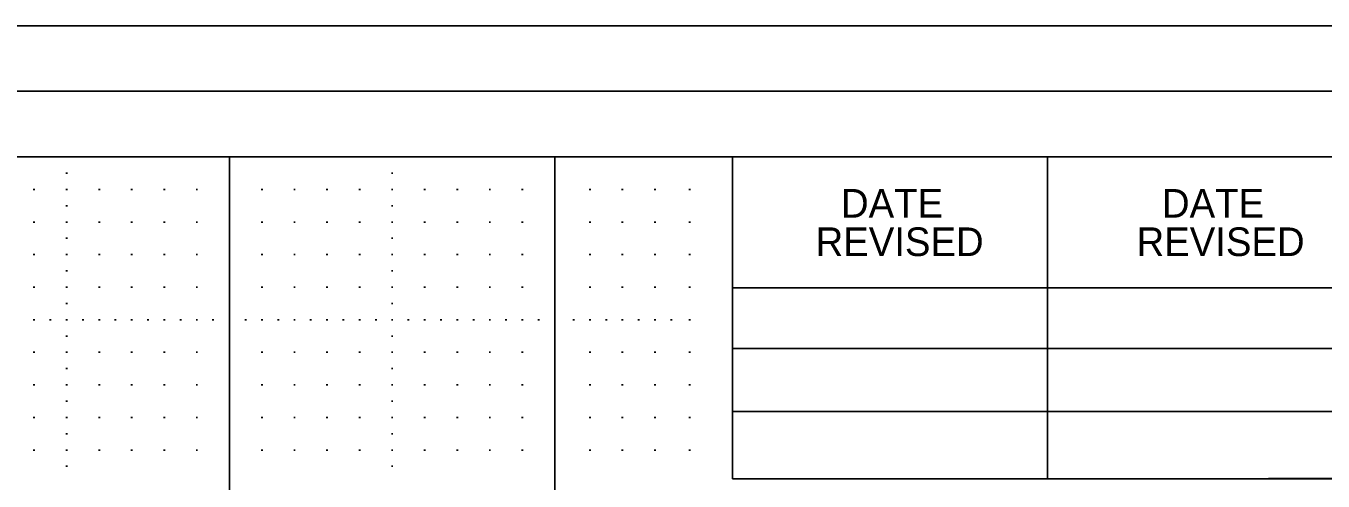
# Model space of a CAD drawing. Extents: x -3.6 to 32.1, y -0.4 to 25.6.
# Drawn here: x 23.183 to 27.168, y 19.55 to 20.947 of the extents above; entities that cross this region are included whole.
import ezdxf

# ---------------------------------------------------------------- set-up
doc = ezdxf.new("R2010")
doc.units = 0
for name, color, linetype in [('Level 1', 7, 'Continuous'), ('Level 4', 7, 'Continuous'), ('Level 5', 7, 'Continuous'), ('Level 62', 7, 'Continuous'), ('Level 63', 7, 'Continuous'), ('Level 63 Full', 7, 'Continuous'), ('R_Border Prem', 7, 'Continuous')]:
    doc.layers.add(name, color=color, linetype=linetype)

msp = doc.modelspace()

# ---------------------------------------------------------------- linework, layer by layer
at = {"layer": 'Level 1'}
for p, q in [((25.353, 19.5569), (25.353, 20.5449)), ((26.321, 19.5569), (26.321, 20.545)), ((25.353, 20.1429), (27.307, 20.1429)), ((25.353, 19.9569), (27.307, 19.9569)), ((25.353, 19.7629), (27.307, 19.7629)), ((31.617, 19.5569), (25.353, 19.5569))]:
    msp.add_line(p, q, dxfattribs=at)
at = {"layer": 'Level 4'}
for p, q in [((23.808, 0.545), (23.808, 20.545)), ((24.808, 0.545), (24.808, 20.5449))]:
    msp.add_line(p, q, dxfattribs=at)
at = {"layer": 'Level 5'}
for p, q in [((23.3055, 20.495), (23.3105, 20.495)), ((24.3055, 20.495), (24.3105, 20.495)), ((23.2055, 20.445), (23.2105, 20.445)), ((23.3055, 20.445), (23.3105, 20.445)), ((23.4055, 20.445), (23.4105, 20.445)), ((23.5055, 20.445), (23.5105, 20.445)), ((23.6055, 20.445), (23.6105, 20.445)), ((23.7055, 20.445), (23.7105, 20.445)), ((23.9055, 20.445), (23.9105, 20.445)), ((24.0055, 20.445), (24.0105, 20.445)), ((24.1055, 20.445), (24.1105, 20.445)), ((24.2055, 20.445), (24.2105, 20.445)), ((24.3055, 20.445), (24.3105, 20.445)), ((24.4055, 20.445), (24.4105, 20.445)), ((24.5055, 20.445), (24.5105, 20.445)), ((24.6055, 20.445), (24.6105, 20.445)), ((24.7055, 20.445), (24.7105, 20.445)), ((24.913, 20.445), (24.918, 20.445)), ((25.013, 20.445), (25.018, 20.445)), ((25.113, 20.445), (25.118, 20.445)), ((25.219, 20.445), (25.224, 20.445)), ((23.3055, 20.395), (23.3105, 20.395)), ((24.3055, 20.395), (24.3105, 20.395)), ((23.2055, 20.345), (23.2105, 20.345)), ((23.3055, 20.345), (23.3105, 20.345)), ((23.4055, 20.345), (23.4105, 20.345)), ((23.5055, 20.345), (23.5105, 20.345)), ((23.6055, 20.345), (23.6105, 20.345)), ((23.7055, 20.345), (23.7105, 20.345)), ((23.9055, 20.345), (23.9105, 20.345)), ((24.0055, 20.345), (24.0105, 20.345)), ((24.1055, 20.345), (24.1105, 20.345)), ((24.2055, 20.345), (24.2105, 20.345)), ((24.3055, 20.345), (24.3105, 20.345)), ((24.4055, 20.345), (24.4105, 20.345)), ((24.5055, 20.345), (24.5105, 20.345)), ((24.6055, 20.345), (24.6105, 20.345)), ((24.7055, 20.345), (24.7105, 20.345)), ((24.913, 20.345), (24.918, 20.345)), ((25.013, 20.345), (25.018, 20.345)), ((25.113, 20.345), (25.118, 20.345)), ((25.219, 20.345), (25.224, 20.345)), ((23.3055, 20.295), (23.3105, 20.295)), ((24.3055, 20.295), (24.3105, 20.295)), ((23.2055, 20.245), (23.2105, 20.245)), ((23.3055, 20.245), (23.3105, 20.245)), ((23.4055, 20.245), (23.4105, 20.245)), ((23.5055, 20.245), (23.5105, 20.245)), ((23.6055, 20.245), (23.6105, 20.245)), ((23.7055, 20.245), (23.7105, 20.245)), ((23.9055, 20.245), (23.9105, 20.245)), ((24.0055, 20.245), (24.0105, 20.245)), ((24.1055, 20.245), (24.1105, 20.245)), ((24.2055, 20.245), (24.2105, 20.245)), ((24.3055, 20.245), (24.3105, 20.245)), ((24.4055, 20.245), (24.4105, 20.245)), ((24.5055, 20.245), (24.5105, 20.245)), ((24.6055, 20.245), (24.6105, 20.245)), ((24.7055, 20.245), (24.7105, 20.245)), ((24.913, 20.245), (24.918, 20.245)), ((25.013, 20.245), (25.018, 20.245)), ((25.113, 20.245), (25.118, 20.245)), ((25.219, 20.245), (25.224, 20.245)), ((23.3055, 20.195), (23.3105, 20.195)), ((24.3055, 20.195), (24.3105, 20.195)), ((23.2055, 20.145), (23.2105, 20.145)), ((23.3055, 20.145), (23.3105, 20.145)), ((23.4055, 20.145), (23.4105, 20.145)), ((23.5055, 20.145), (23.5105, 20.145)), ((23.6055, 20.145), (23.6105, 20.145)), ((23.7055, 20.145), (23.7105, 20.145)), ((23.9055, 20.145), (23.9105, 20.145)), ((24.0055, 20.145), (24.0105, 20.145)), ((24.1055, 20.145), (24.1105, 20.145)), ((24.2055, 20.145), (24.2105, 20.145)), ((24.3055, 20.145), (24.3105, 20.145)), ((24.4055, 20.145), (24.4105, 20.145)), ((24.5055, 20.145), (24.5105, 20.145)), ((24.6055, 20.145), (24.6105, 20.145)), ((24.7055, 20.145), (24.7105, 20.145)), ((24.913, 20.145), (24.918, 20.145)), ((25.013, 20.145), (25.018, 20.145)), ((25.113, 20.145), (25.118, 20.145)), ((25.219, 20.145), (25.224, 20.145)), ((23.3055, 20.095), (23.3105, 20.095)), ((24.3055, 20.095), (24.3105, 20.095)), ((23.2055, 20.045), (23.2105, 20.045)), ((23.2555, 20.045), (23.2605, 20.045)), ((23.3055, 20.045), (23.3105, 20.045)), ((23.3555, 20.045), (23.3605, 20.045)), ((23.4055, 20.045), (23.4105, 20.045)), ((23.4555, 20.045), (23.4605, 20.045)), ((23.5055, 20.045), (23.5105, 20.045)), ((23.5555, 20.045), (23.5605, 20.045)), ((23.6055, 20.045), (23.6105, 20.045)), ((23.6555, 20.045), (23.6605, 20.045)), ((23.7055, 20.045), (23.7105, 20.045)), ((23.7555, 20.045), (23.7605, 20.045)), ((23.8555, 20.045), (23.8605, 20.045)), ((23.9055, 20.045), (23.9105, 20.045)), ((23.9555, 20.045), (23.9605, 20.045)), ((24.0055, 20.045), (24.0105, 20.045)), ((24.0555, 20.045), (24.0605, 20.045)), ((24.1055, 20.045), (24.1105, 20.045)), ((24.1555, 20.045), (24.1605, 20.045)), ((24.2055, 20.045), (24.2105, 20.045)), ((24.2555, 20.045), (24.2605, 20.045)), ((24.3055, 20.045), (24.3105, 20.045)), ((24.3555, 20.045), (24.3605, 20.045)), ((24.4055, 20.045), (24.4105, 20.045)), ((24.4555, 20.045), (24.4605, 20.045)), ((24.5055, 20.045), (24.5105, 20.045)), ((24.5555, 20.045), (24.5605, 20.045)), ((24.6055, 20.045), (24.6105, 20.045)), ((24.6555, 20.045), (24.6605, 20.045)), ((24.7055, 20.045), (24.7105, 20.045)), ((24.7555, 20.045), (24.7605, 20.045)), ((24.863, 20.045), (24.868, 20.045)), ((24.913, 20.045), (24.918, 20.045)), ((24.963, 20.045), (24.968, 20.045)), ((25.013, 20.045), (25.018, 20.045)), ((25.063, 20.045), (25.068, 20.045)), ((25.113, 20.045), (25.118, 20.045)), ((25.163, 20.045), (25.168, 20.045)), ((25.219, 20.045), (25.224, 20.045)), ((23.3055, 19.995), (23.3105, 19.995)), ((24.3055, 19.995), (24.3105, 19.995)), ((23.2055, 19.945), (23.2105, 19.945)), ((23.3055, 19.945), (23.3105, 19.945)), ((23.4055, 19.945), (23.4105, 19.945)), ((23.5055, 19.945), (23.5105, 19.945)), ((23.6055, 19.945), (23.6105, 19.945)), ((23.7055, 19.945), (23.7105, 19.945)), ((23.9055, 19.945), (23.9105, 19.945)), ((24.0055, 19.945), (24.0105, 19.945)), ((24.1055, 19.945), (24.1105, 19.945)), ((24.2055, 19.945), (24.2105, 19.945)), ((24.3055, 19.945), (24.3105, 19.945)), ((24.4055, 19.945), (24.4105, 19.945)), ((24.5055, 19.945), (24.5105, 19.945)), ((24.6055, 19.945), (24.6105, 19.945)), ((24.7055, 19.945), (24.7105, 19.945)), ((24.913, 19.945), (24.918, 19.945)), ((25.013, 19.945), (25.018, 19.945)), ((25.113, 19.945), (25.118, 19.945)), ((25.219, 19.945), (25.224, 19.945)), ((23.3055, 19.895), (23.3105, 19.895)), ((24.3055, 19.895), (24.3105, 19.895)), ((23.2055, 19.845), (23.2105, 19.845)), ((23.3055, 19.845), (23.3105, 19.845)), ((23.4055, 19.845), (23.4105, 19.845)), ((23.5055, 19.845), (23.5105, 19.845)), ((23.6055, 19.845), (23.6105, 19.845)), ((23.7055, 19.845), (23.7105, 19.845)), ((23.9055, 19.845), (23.9105, 19.845)), ((24.0055, 19.845), (24.0105, 19.845)), ((24.1055, 19.845), (24.1105, 19.845)), ((24.2055, 19.845), (24.2105, 19.845)), ((24.3055, 19.845), (24.3105, 19.845)), ((24.4055, 19.845), (24.4105, 19.845)), ((24.5055, 19.845), (24.5105, 19.845)), ((24.6055, 19.845), (24.6105, 19.845)), ((24.7055, 19.845), (24.7105, 19.845)), ((24.913, 19.845), (24.918, 19.845)), ((25.013, 19.845), (25.018, 19.845)), ((25.113, 19.845), (25.118, 19.845)), ((25.219, 19.845), (25.224, 19.845)), ((23.3055, 19.795), (23.3105, 19.795)), ((24.3055, 19.795), (24.3105, 19.795)), ((23.2055, 19.745), (23.2105, 19.745)), ((23.3055, 19.745), (23.3105, 19.745)), ((23.4055, 19.745), (23.4105, 19.745)), ((23.5055, 19.745), (23.5105, 19.745)), ((23.6055, 19.745), (23.6105, 19.745)), ((23.7055, 19.745), (23.7105, 19.745)), ((23.9055, 19.745), (23.9105, 19.745)), ((24.0055, 19.745), (24.0105, 19.745)), ((24.1055, 19.745), (24.1105, 19.745)), ((24.2055, 19.745), (24.2105, 19.745)), ((24.3055, 19.745), (24.3105, 19.745)), ((24.4055, 19.745), (24.4105, 19.745)), ((24.5055, 19.745), (24.5105, 19.745)), ((24.6055, 19.745), (24.6105, 19.745)), ((24.7055, 19.745), (24.7105, 19.745)), ((24.913, 19.745), (24.918, 19.745)), ((25.013, 19.745), (25.018, 19.745)), ((25.113, 19.745), (25.118, 19.745)), ((25.219, 19.745), (25.224, 19.745)), ((23.3055, 19.695), (23.3105, 19.695)), ((24.3055, 19.695), (24.3105, 19.695)), ((23.2055, 19.645), (23.2105, 19.645)), ((23.3055, 19.645), (23.3105, 19.645)), ((23.4055, 19.645), (23.4105, 19.645)), ((23.5055, 19.645), (23.5105, 19.645)), ((23.6055, 19.645), (23.6105, 19.645)), ((23.7055, 19.645), (23.7105, 19.645)), ((23.9055, 19.645), (23.9105, 19.645)), ((24.0055, 19.645), (24.0105, 19.645)), ((24.1055, 19.645), (24.1105, 19.645)), ((24.2055, 19.645), (24.2105, 19.645)), ((24.3055, 19.645), (24.3105, 19.645)), ((24.4055, 19.645), (24.4105, 19.645)), ((24.5055, 19.645), (24.5105, 19.645)), ((24.6055, 19.645), (24.6105, 19.645)), ((24.7055, 19.645), (24.7105, 19.645)), ((24.913, 19.645), (24.918, 19.645)), ((25.013, 19.645), (25.018, 19.645)), ((25.113, 19.645), (25.118, 19.645)), ((25.219, 19.645), (25.224, 19.645)), ((23.3055, 19.595), (23.3105, 19.595)), ((24.3055, 19.595), (24.3105, 19.595))]:
    msp.add_line(p, q, dxfattribs=at)
at = {"layer": 'Level 62'}
for p, q in [((25.353, 19.5569), (25.353, 20.5449)), ((26.9998, 19.558), (25.353, 19.5569)), ((30.8075, 19.5579), (26.9998, 19.558)), ((26.9998, 19.558), (26.9998, 19.558)), ((26.9998, 19.558), (26.9998, 19.558)), ((26.9998, 19.558), (26.9998, 19.558))]:
    msp.add_line(p, q, dxfattribs=at)
msp.add_lwpolyline([(25.353, 20.5449), (25.353, 20.5449), (25.353, 20.5449), (0.808, 20.545)], dxfattribs=at)
at = {"layer": 'Level 63'}
msp.add_lwpolyline([(-1.263, -0.2005), (32.067, -0.2005), (32.067, 20.7465), (-1.263, 20.7465)], close=True, dxfattribs=at)
at = {"layer": 'Level 63 Full'}
msp.add_lwpolyline([(32.017, -0.403), (-3.583, -0.403), (-3.583, 20.947), (32.017, 20.947)], close=True, dxfattribs=at)
at = {"layer": 'R_Border Prem'}
msp.add_line((-0.001, 20.545), (31.617, 20.545), dxfattribs=at)

# ---------------------------------------------------------------- texts
at = {"layer": 'Level 1'}
for s, p in [('DATE', (25.6868, 20.3586)), ('DATE', (26.6728, 20.3586)), ('REVISED', (25.6088, 20.2406)), ('REVISED', (26.5948, 20.2406))]:
    msp.add_text(s, height=0.08792, dxfattribs=at).set_placement(p)

doc.saveas('drawing.dxf')
